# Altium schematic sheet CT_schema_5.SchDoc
size 467 x 267 mm
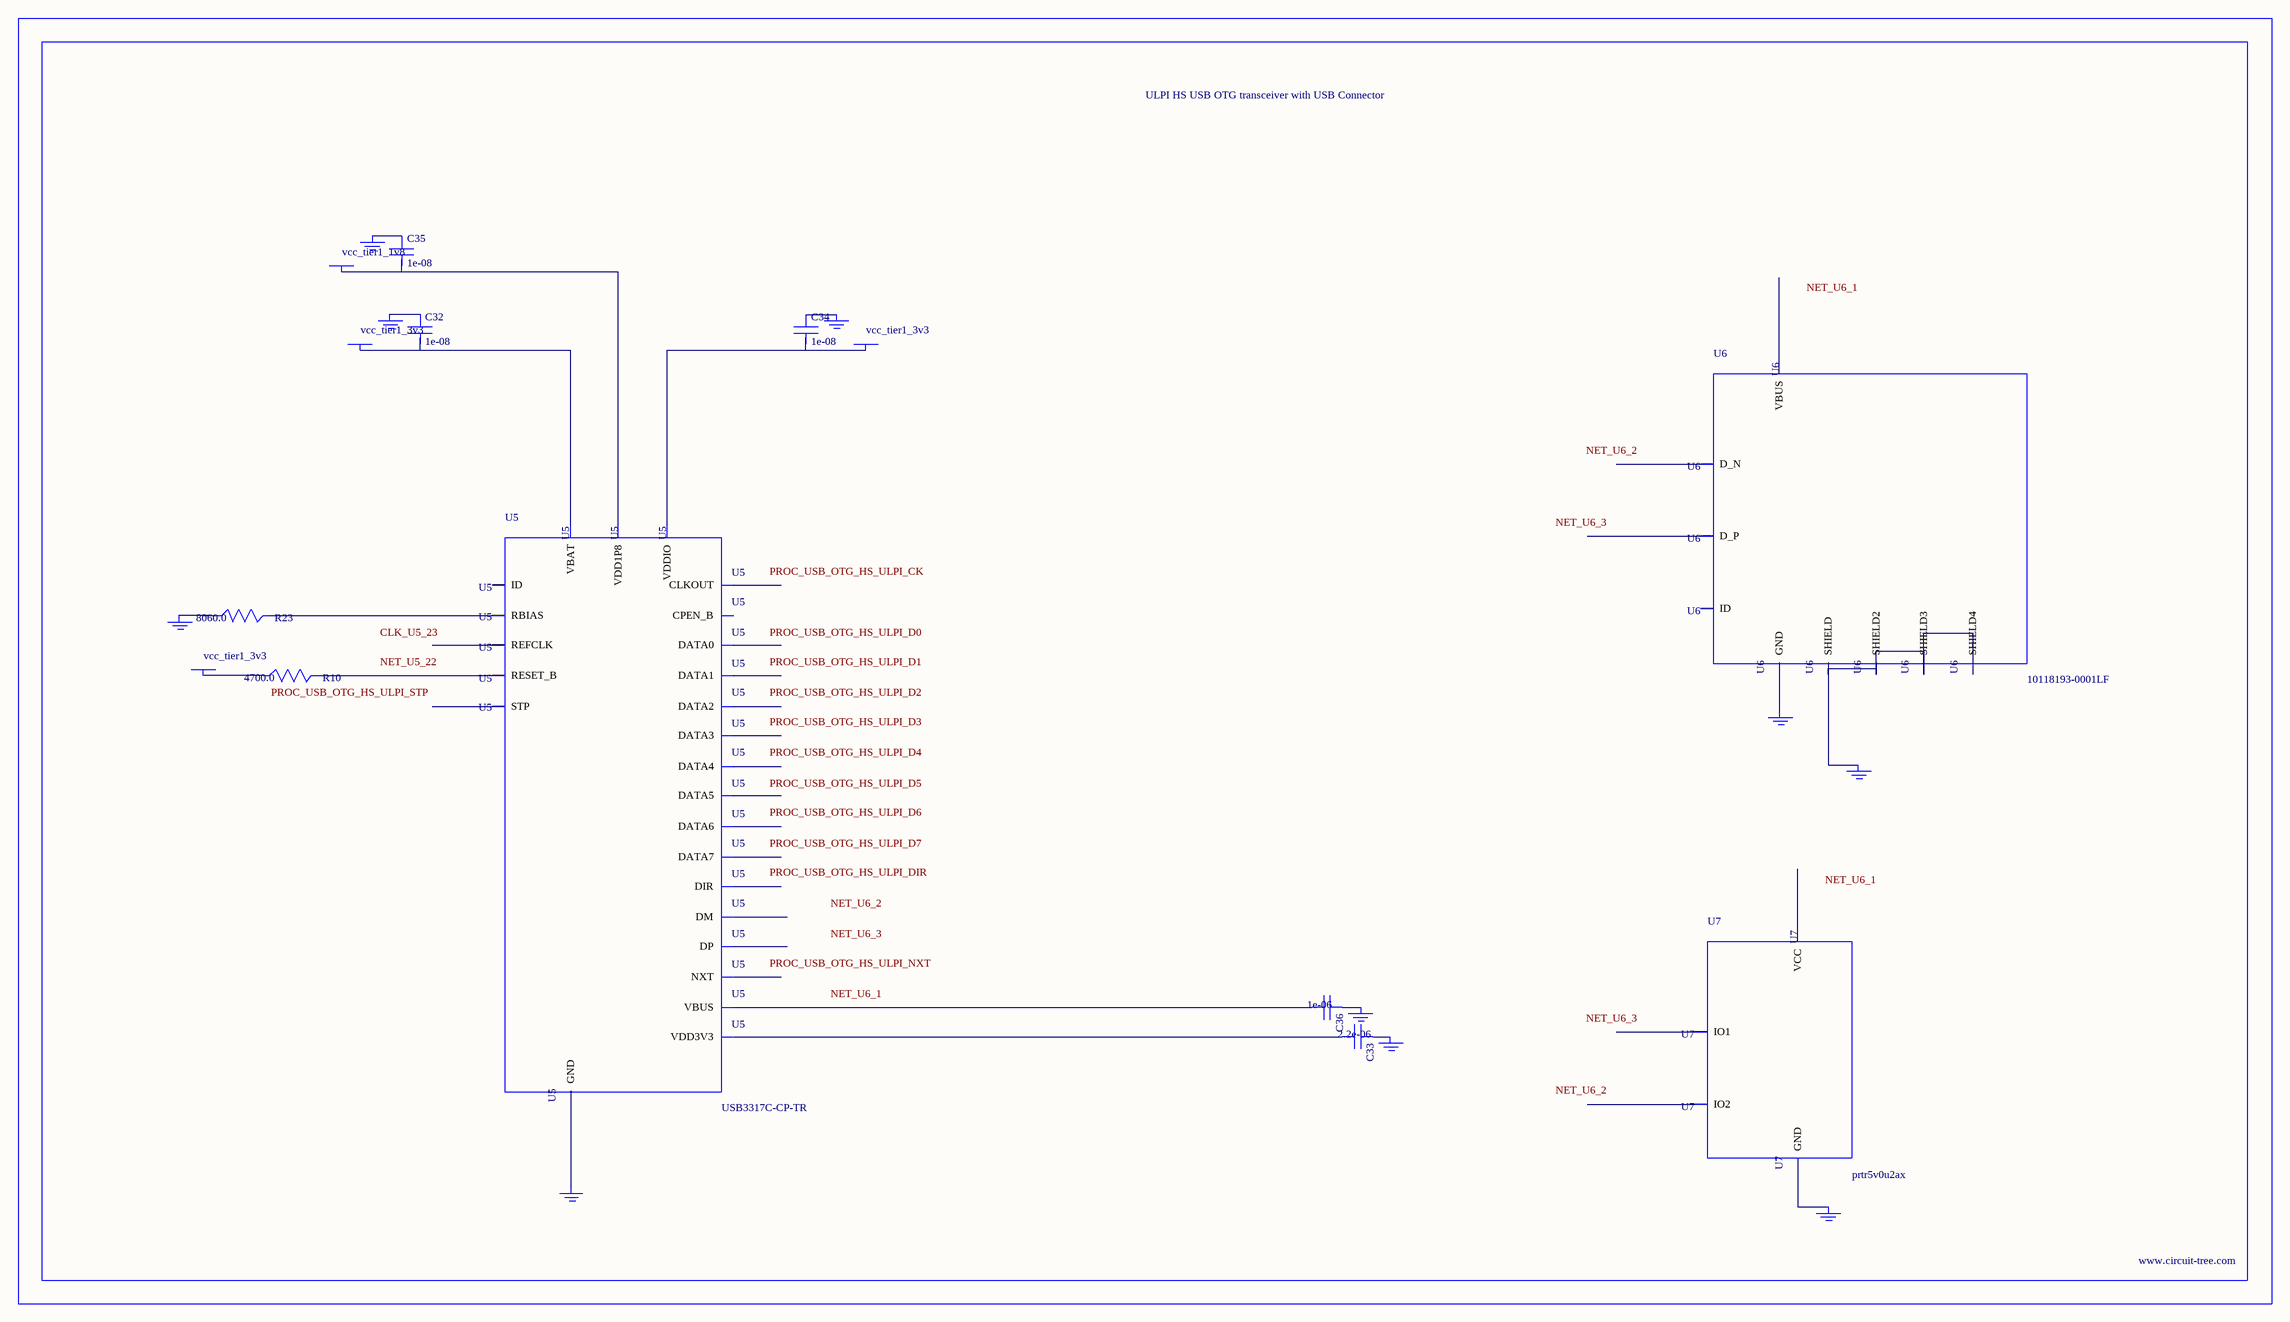
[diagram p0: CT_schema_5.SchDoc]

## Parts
BORDER4  (no value)
C32  1e-08  [C0402]
C33  2.2e-06  [C0603]
C34  1e-08  [C0402]
C35  1e-08  [C0402]
C36  1e-06  [C0603]
GND_INSTANCE_4_0  (no value)
GND_INSTANCE_4_1  (no value)
GND_INSTANCE_4_2  (no value)
GND_INSTANCE_4_3  (no value)
GND_INSTANCE_4_4  (no value)
GND_INSTANCE_4_5  (no value)
GND_INSTANCE_4_6  (no value)
GND_INSTANCE_4_7  (no value)
GND_INSTANCE_4_8  (no value)
GND_INSTANCE_4_9  (no value)
POWER_INSTANCE_4_0  vcc_tier1_3v3
POWER_INSTANCE_4_1  vcc_tier1_3v3
POWER_INSTANCE_4_2  vcc_tier1_1v8
POWER_INSTANCE_4_3  vcc_tier1_3v3
R10  4700.0  [R0603]
R23  8060.0  [R0603]
U5  USB3317C-CP-TR  [QFN-24]
U6  10118193-0001LF  [FCI_10118193-0001LF]
U7  prtr5v0u2ax  [SOT143B]

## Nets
NetC32_1: C32.1 GND_INSTANCE_4_1.0(GND)
NetC32_2: C32.2 POWER_INSTANCE_4_0.0(PWR) U5.3(VBAT)
NetC33_1: C33.1 GND_INSTANCE_4_2.0(GND)
NetC33_2: C33.2 U5.4(VDD3V3)
NetC34_1: C34.1 GND_INSTANCE_4_3.0(GND)
NetC34_2: C34.2 POWER_INSTANCE_4_1.0(PWR) U5.17(VDDIO)
NetC35_1: C35.1 GND_INSTANCE_4_4.0(GND)
NetC35_2: C35.2 POWER_INSTANCE_4_2.0(PWR) U5.21(VDD1P8)
NetC36_1: C36.1 GND_INSTANCE_4_0.0(GND)
NetC36_2: C36.2 U5.2(VBUS)
NetGND_INSTANCE_4_5_0: GND_INSTANCE_4_5.0(GND) R23.1
NetGND_INSTANCE_4_6_0: GND_INSTANCE_4_6.0(GND) U5.25(GND)
NetGND_INSTANCE_4_7_0: GND_INSTANCE_4_7.0(GND) U6.6(SHIELD) U6.7(SHIELD2) U6.8(SHIELD3) U6.9(SHIELD4)
NetGND_INSTANCE_4_8_0: GND_INSTANCE_4_8.0(GND) U6.5(GND)
NetGND_INSTANCE_4_9_0: GND_INSTANCE_4_9.0(GND) U7.1(GND)
NetPOWER_INSTANCE_4_3_0: POWER_INSTANCE_4_3.0(PWR) R10.1
NetR10_2: R10.2 U5.22(RESET_B)
NetR23_2: R23.2 U5.24(RBIAS)

Not connected (* = marked no-connect by the designer): U5 1(ID) 5(DM) 6(DP) 7(CPEN_B) 8(DATA7) 9(DATA6) 10(DATA5) 11(DATA4) 12(CLKOUT) 13(DATA3) 14(DATA2) 15(DATA1) 16(DATA0) 18(NXT) 19(DIR) 20(STP) 23(REFCLK); U6 1(VBUS) 2(D_N) 3(D_P) 4(ID); U7 2(IO1) 3(IO2) 4(VCC)

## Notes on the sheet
- Labels drawn without touching a wire or pin: CLK_U5_23, NET_U5_22, NET_U6_1, NET_U6_2, NET_U6_3, PROC_USB_OTG_HS_ULPI_CK, PROC_USB_OTG_HS_ULPI_D0, PROC_USB_OTG_HS_ULPI_D1, PROC_USB_OTG_HS_ULPI_D2, PROC_USB_OTG_HS_ULPI_D3, PROC_USB_OTG_HS_ULPI_D4, PROC_USB_OTG_HS_ULPI_D5, PROC_USB_OTG_HS_ULPI_D6, PROC_USB_OTG_HS_ULPI_D7, PROC_USB_OTG_HS_ULPI_DIR, PROC_USB_OTG_HS_ULPI_NXT, PROC_USB_OTG_HS_ULPI_STP

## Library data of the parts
BORDER4 = BORDER_PAGE4
C32 C34 C35 = C0402C103K3RAC
C33 = C0603C225K8RACTU
C36 = C0603C105K3RACTU
GND_INSTANCE_4_0-GND_INSTANCE_4_9 = GND
POWER_INSTANCE_4_0-POWER_INSTANCE_4_3 = PWR
R10 = RC0603JR-074K7L
R23 = ERJ-3EKF8061V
